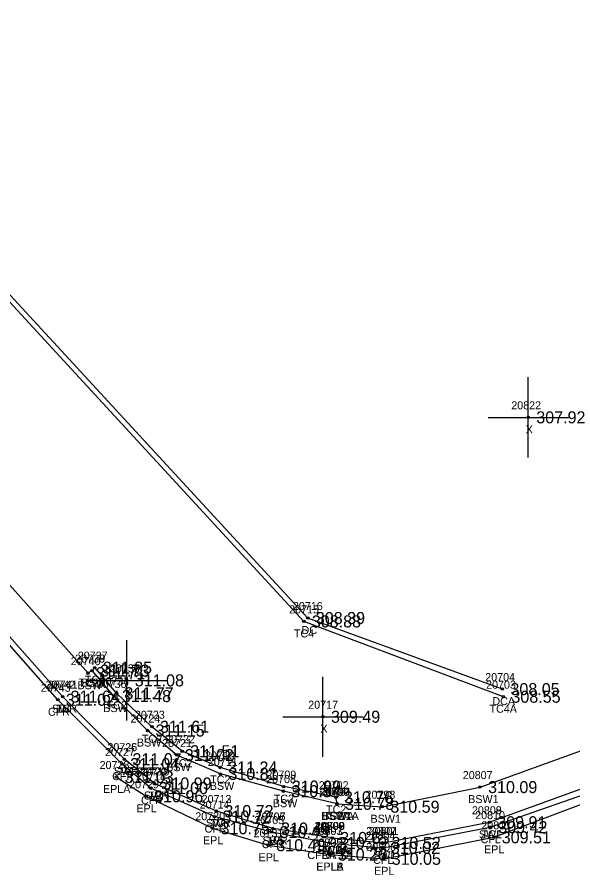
# Model space of a CAD drawing. Extents: x 1970242 to 1971082, y 803104 to 803947.
# Drawn here: x 1970579.6 to 1970648.9, y 803614.4 to 803721.5 of the extents above; entities that cross this region are included whole.
import ezdxf

# ---------------------------------------------------------------- set-up
doc = ezdxf.new("R2010")
doc.units = 0
for name, color, linetype in [('RD_DTM_BkLn2', 7, 'Continuous'), ('RD_EX_Conc', 7, 'Continuous'), ('RD_EX_Conc_txCode', 7, 'Continuous'), ('RD_EX_Misc', 7, 'Continuous'), ('RD_EX_Misc_txCode', 7, 'Continuous'), ('RD_EX_Road', 7, 'Continuous'), ('RD_EX_Road_txCode', 7, 'Continuous'), ('RD_EX_TX_Conc_ELEV', 7, 'Continuous'), ('RD_EX_TX_Misc_ELEV', 7, 'Continuous'), ('RD_EX_TX_Road_ELEV', 7, 'Continuous'), ('RD_SMD_Locator', 7, 'Continuous')]:
    doc.layers.add(name, color=color, linetype=linetype)

msp = doc.modelspace()

# ---------------------------------------------------------------- linework, layer by layer
at = {"layer": 'RD_DTM_BkLn2'}
for points in [[(1970640.22, 803636.65), (1970615.32, 803646.05), (1970567.96, 803697.44), (1970561.94, 803699.47), (1970557.33, 803698.89), (1970545.39, 803690.43), (1970544.29, 803690.54)], [(1970618.86, 803619.02), (1970611.49, 803620.2), (1970604.41, 803622.38), (1970596.68, 803625.82), (1970592.94, 803628.85), (1970585.22, 803636.66), (1970542.35, 803685.17), (1970541.56, 803686.12)], [(1970618.86, 803619.02), (1970625.27, 803618.4), (1970638.45, 803620.98), (1970653.93, 803626.63), (1970665.79, 803631.9), (1970699.28, 803647.11), (1970716.76, 803654.07), (1970733.36, 803660.46), (1970737.6, 803661.87)], [(1970619.46, 803623.28), (1970619.33, 803624.1), (1970612.82, 803625.43), (1970604.88, 803627.82), (1970600.14, 803629.85), (1970596.37, 803632.9), (1970591.95, 803637.08), (1970589.24, 803640.28), (1970588.91, 803639.91)]]:
    msp.add_lwpolyline(points, dxfattribs=at)
at = {"layer": 'RD_EX_Conc'}
for points in [[(1970640.1, 803637.6), (1970615.82, 803646.47), (1970568.4, 803697.87), (1970561.49, 803700.09), (1970556.78, 803699.45), (1970544.29, 803690.54)], [(1970619.46, 803623.28), (1970612.77, 803624.86), (1970604.91, 803627.02), (1970599.47, 803629.36), (1970595.82, 803632.43), (1970591.62, 803636.73), (1970588.91, 803639.91), (1970588.4, 803639.59), (1970556.38, 803675.53), (1970556.93, 803675.97), (1970554.39, 803679.06), (1970544.29, 803690.54)], [(1970618.57, 803618.39), (1970611.3, 803619.75), (1970604.17, 803621.69), (1970596.23, 803625.24), (1970592.64, 803628.24), (1970584.63, 803636.27), (1970541.45, 803685.26)], [(1970618.86, 803619.02), (1970611.49, 803620.2), (1970604.41, 803622.38), (1970596.68, 803625.82), (1970592.94, 803628.85), (1970585.22, 803636.66), (1970542.35, 803685.17), (1970541.56, 803686.12)], [(1970619.46, 803623.28), (1970625.12, 803622.92), (1970637.31, 803625.37), (1970651.91, 803630.64), (1970663.49, 803635.69), (1970697.74, 803651.1), (1970715.31, 803658.28), (1970731.61, 803664.68), (1970736.58, 803666.33)], [(1970618.86, 803619.02), (1970625.27, 803618.4), (1970638.45, 803620.98), (1970653.93, 803626.63), (1970665.79, 803631.9), (1970699.28, 803647.11), (1970716.76, 803654.07), (1970733.36, 803660.46), (1970737.6, 803661.87)], [(1970618.57, 803618.39), (1970625.17, 803617.79), (1970638.58, 803620.37), (1970654.08, 803625.78), (1970666.26, 803631.23), (1970699.41, 803646.5), (1970717.02, 803653.29), (1970733.54, 803659.83), (1970737.45, 803661.48)]]:
    msp.add_lwpolyline(points, dxfattribs=at)
at = {"layer": 'RD_EX_Misc'}
for p, q in [((1970643.32, 803666.52), (1970643.32, 803676.52)), ((1970638.32, 803671.52), (1970648.32, 803671.52)), ((1970593.23, 803633.69), (1970593.23, 803643.69)), ((1970617.71, 803629.15), (1970617.71, 803639.15)), ((1970588.23, 803638.69), (1970598.23, 803638.69)), ((1970612.71, 803634.15), (1970622.71, 803634.15))]:
    msp.add_line(p, q, dxfattribs=at)
at = {"layer": 'RD_EX_Road'}
msp.add_lwpolyline([(1970591.95, 803626.63), (1970595.64, 803624.22), (1970603.94, 803620.23), (1970610.89, 803618.12), (1970618.56, 803616.95), (1970618.56, 803616.95), (1970625.29, 803616.42), (1970639.01, 803619.1), (1970654.35, 803624.92), (1970666.82, 803630.04), (1970700.04, 803645.21), (1970717.46, 803652.2), (1970737.46, 803660.02), (1970785.58, 803677.59), (1970806.16, 803685.61), (1970810.51, 803687.07), (1970832.41, 803695.41), (1970845.91, 803700.39), (1970902.88, 803721.47)], dxfattribs=at)
at = {"layer": 'RD_SMD_Locator'}
for centre in [(1970643.32, 803671.52), (1970615.82, 803646.47), (1970615.32, 803646.05), (1970589.24, 803640.28), (1970588.4, 803639.59), (1970588.91, 803639.91), (1970588.91, 803639.91), (1970593.23, 803638.69), (1970591.95, 803637.08), (1970640.1, 803637.6), (1970584.63, 803636.27), (1970585.22, 803636.66), (1970585.22, 803636.66), (1970591.62, 803636.73), (1970640.22, 803636.65), (1970617.71, 803634.15), (1970596.37, 803632.9), (1970595.82, 803632.43), (1970599.47, 803629.36), (1970600.14, 803629.85), (1970592.94, 803628.85), (1970592.94, 803628.85), (1970592.64, 803628.24), (1970604.88, 803627.82), (1970591.95, 803626.63), (1970604.91, 803627.02), (1970596.23, 803625.24), (1970596.68, 803625.82), (1970596.68, 803625.82), (1970612.82, 803625.43), (1970637.31, 803625.37), (1970595.64, 803624.22), (1970612.77, 803624.86), (1970619.33, 803624.1), (1970619.46, 803623.28), (1970619.46, 803623.28), (1970619.46, 803623.28), (1970625.12, 803622.92), (1970604.41, 803622.38), (1970604.41, 803622.38), (1970604.17, 803621.69), (1970638.45, 803620.98), (1970638.45, 803620.98), (1970603.94, 803620.23), (1970611.3, 803619.75), (1970611.49, 803620.2), (1970611.49, 803620.2), (1970638.58, 803620.37), (1970618.86, 803619.02), (1970618.86, 803619.02), (1970618.86, 803619.02), (1970618.86, 803619.02), (1970639.01, 803619.1), (1970610.89, 803618.12), (1970618.57, 803618.39), (1970618.57, 803618.39), (1970625.17, 803617.79), (1970625.27, 803618.4), (1970625.27, 803618.4), (1970618.56, 803616.95), (1970618.56, 803616.95), (1970625.29, 803616.42)]:
    msp.add_circle(centre, 0.15, dxfattribs=at)

# ---------------------------------------------------------------- texts
at = {"layer": 'RD_EX_Conc_txCode'}
for s, p in [('20715', (1970613.49, 803647.05)), ('20716', (1970613.96, 803647.47)), ('TC4', (1970614.08, 803644.05)), ('DC', (1970615.04, 803644.47)), ('20740', (1970586.24, 803640.59)), ('20738', (1970586.79, 803640.91)), ('20739', (1970586.79, 803640.91)), ('20737', (1970587.12, 803641.28)), ('TC2', (1970588, 803638.28)), ('20704', (1970637.95, 803638.6)), ('20743', (1970582.51, 803637.27)), ('20742', (1970583.1, 803637.66)), ('20741', (1970583.38, 803637.66)), ('BSW', (1970587.08, 803637.59)), ('TC2B', (1970587.19, 803637.91)), ('BSW', (1970587.59, 803637.91)), ('20736', (1970589.48, 803637.73)), ('20734', (1970589.83, 803638.08)), ('20703', (1970638.06, 803637.65)), ('TC2', (1970590.71, 803635.08)), ('DCA', (1970638.84, 803635.6)), ('CFR', (1970583.4, 803634.27)), ('SWR', (1970583.9, 803634.66)), ('TC', (1970584.42, 803634.66)), ('BSW', (1970590.3, 803634.73)), ('20723', (1970594.25, 803633.9)), ('TC4A', (1970638.49, 803634.65)), ('20724', (1970593.7, 803633.43)), ('TC2', (1970595.12, 803630.9)), ('20722', (1970598.02, 803630.85)), ('20726', (1970590.8, 803629.85)), ('20725', (1970590.82, 803629.85)), ('BSW', (1970594.5, 803630.43)), ('20721', (1970597.64, 803630.36)), ('20727', (1970590.52, 803629.24)), ('20710', (1970603, 803628.82)), ('TC2', (1970598.9, 803627.85)), ('20711', (1970603.35, 803628.02)), ('SWR', (1970591.62, 803626.85)), ('TC', (1970592.14, 803626.85)), ('20720', (1970594.53, 803626.82)), ('20719', (1970594.85, 803626.82)), ('BSW', (1970598.16, 803627.36)), ('20709', (1970610.66, 803626.43)), ('20807', (1970635.15, 803626.37)), ('CFR', (1970591.41, 803626.24)), ('20718', (1970594.4, 803626.24)), ('TC2', (1970603.63, 803625.82)), ('20708', (1970610.62, 803625.86)), ('BSW', (1970603.59, 803625.02)), ('20702', (1970617.18, 803625.1)), ('20700', (1970617.26, 803624.28)), ('20797', (1970617.34, 803624.28)), ('20701', (1970617.58, 803624.28)), ('CFR', (1970595, 803623.24)), ('SWR', (1970595.37, 803623.82)), ('TC', (1970595.89, 803623.82)), ('20712', (1970602.57, 803623.38)), ('20713', (1970602.57, 803623.38)), ('TC2', (1970611.57, 803623.43)), ('20798', (1970623.01, 803623.92)), ('BSW1', (1970635.82, 803623.37)), ('20714', (1970602.33, 803622.69)), ('BSW', (1970611.46, 803622.86)), ('TC2', (1970618.09, 803622.1)), ('20706', (1970609.31, 803621.2)), ('20707', (1970609.33, 803621.2)), ('BSW1A', (1970617.49, 803621.28)), ('BSWA', (1970617.65, 803621.28)), ('TC2A', (1970617.73, 803621.28)), ('20808', (1970636.29, 803621.98)), ('20809', (1970636.29, 803621.98)), ('20810', (1970636.7, 803621.37)), ('SWR', (1970603.09, 803620.38)), ('TC', (1970603.61, 803620.38)), ('20705', (1970609.15, 803620.75)), ('20800', (1970616.66, 803620.02)), ('20698', (1970616.71, 803620.02)), ('20699', (1970616.71, 803620.02)), ('20799', (1970616.74, 803620.02)), ('BSW1', (1970623.64, 803620.92)), ('CFR', (1970602.94, 803619.69)), ('20803', (1970616.41, 803619.39)), ('20697', (1970616.43, 803619.39)), ('20802', (1970623.11, 803619.4)), ('20801', (1970623.4, 803619.4)), ('SWL', (1970637.16, 803618.98)), ('TC1', (1970637.49, 803618.98)), ('CFR', (1970610.07, 803617.75)), ('SWR', (1970610.17, 803618.2)), ('TC', (1970610.69, 803618.2)), ('20804', (1970623.01, 803618.79)), ('CFL', (1970637.37, 803618.37)), ('SWRA', (1970617.05, 803617.02)), ('SWLA', (1970617.08, 803617.02)), ('TC1A', (1970617.41, 803617.02)), ('TCA', (1970617.57, 803617.02)), ('CFRA 12', (1970615.75, 803616.39)), ('CFLA 12', (1970615.77, 803616.39)), ('CFL', (1970623.96, 803615.79)), ('SWL', (1970623.98, 803616.4)), ('TC1', (1970624.31, 803616.4))]:
    msp.add_text(s, height=1, dxfattribs=at).set_placement(p)
at = {"layer": 'RD_EX_Misc_txCode'}
for s, p in [('20822', (1970641.2, 803672.52)), ('X', (1970643, 803669.52)), ('20735', (1970591.12, 803639.69)), ('X', (1970592.92, 803636.69)), ('20717', (1970615.87, 803635.15)), ('X', (1970617.39, 803632.15))]:
    msp.add_text(s, height=1, dxfattribs=at).set_placement(p)
at = {"layer": 'RD_EX_Road_txCode'}
for s, p in [('20728', (1970589.84, 803627.63)), ('EPLA', (1970590.26, 803624.63)), ('20729', (1970593.52, 803625.22)), ('EPL', (1970594.43, 803622.22)), ('20730', (1970601.78, 803621.23)), ('20811', (1970637.46, 803620.1)), ('20731', (1970609.05, 803619.12)), ('EPL', (1970602.74, 803618.23)), ('20805', (1970616.4, 803617.95)), ('20732', (1970616.44, 803617.95)), ('20806', (1970623.11, 803617.42)), ('EPL', (1970637.8, 803617.1)), ('EPL', (1970609.68, 803616.12)), ('EPLA', (1970616.86, 803614.95)), ('EPLB', (1970616.88, 803614.95)), ('EPL', (1970624.08, 803614.42))]:
    msp.add_text(s, height=1, dxfattribs=at).set_placement(p)
at = {"layer": 'RD_EX_TX_Conc_ELEV'}
for s, p in [('308.88', (1970616.32, 803645.3)), ('308.39', (1970616.82, 803645.72)), ('311.71', (1970589.4, 803638.84)), ('311.73', (1970589.91, 803639.16)), ('311.73', (1970589.91, 803639.16)), ('311.85', (1970590.24, 803639.53)), ('308.05', (1970641.1, 803636.85)), ('311.02', (1970585.63, 803635.52)), ('311.64', (1970586.22, 803635.91)), ('311.64', (1970586.22, 803635.91)), ('311.48', (1970592.62, 803635.98)), ('311.77', (1970592.95, 803636.33)), ('308.55', (1970641.22, 803635.9)), ('311.15', (1970596.82, 803631.68)), ('311.61', (1970597.37, 803632.15)), ('311.51', (1970601.14, 803629.1)), ('311.07', (1970593.94, 803628.1)), ('311.07', (1970593.94, 803628.1)), ('311.02', (1970600.47, 803628.61)), ('311.04', (1970593.64, 803627.49)), ('311.24', (1970605.88, 803627.07)), ('310.81', (1970605.91, 803626.27)), ('310.99', (1970597.68, 803625.07)), ('310.99', (1970597.68, 803625.07)), ('311.00', (1970597.23, 803624.49)), ('310.54', (1970613.77, 803624.11)), ('310.99', (1970613.82, 803624.68)), ('310.09', (1970638.31, 803624.62)), ('310.76', (1970620.33, 803623.35)), ('310.72', (1970605.41, 803621.63)), ('310.72', (1970605.41, 803621.63)), ('310.78', (1970620.46, 803622.53)), ('310.78', (1970620.46, 803622.53)), ('310.78', (1970620.46, 803622.53)), ('310.59', (1970626.12, 803622.17)), ('310.72', (1970605.17, 803620.94)), ('310.49', (1970612.49, 803619.45)), ('310.49', (1970612.49, 803619.45)), ('309.91', (1970639.45, 803620.23)), ('309.91', (1970639.45, 803620.23)), ('309.42', (1970639.58, 803619.62)), ('310.45', (1970612.3, 803619)), ('310.19', (1970619.57, 803617.64)), ('310.19', (1970619.57, 803617.64)), ('310.65', (1970619.86, 803618.27)), ('310.65', (1970619.86, 803618.27)), ('310.65', (1970619.86, 803618.27)), ('310.65', (1970619.86, 803618.27)), ('310.52', (1970626.27, 803617.65)), ('310.52', (1970626.27, 803617.65)), ('310.02', (1970626.17, 803617.04))]:
    msp.add_text(s, height=1.5, dxfattribs=at).set_placement(p)
at = {"layer": 'RD_EX_TX_Misc_ELEV'}
for s, p in [('307.92', (1970644.32, 803670.77)), ('311.08', (1970594.23, 803637.94)), ('309.49', (1970618.71, 803633.4))]:
    msp.add_text(s, height=1.5, dxfattribs=at).set_placement(p)
at = {"layer": 'RD_EX_TX_Road_ELEV'}
for s, p in [('311.03', (1970592.95, 803625.88)), ('310.96', (1970596.64, 803623.47)), ('310.75', (1970604.94, 803619.48)), ('309.51', (1970640.01, 803618.35)), ('310.49', (1970611.89, 803617.37)), ('310.26', (1970619.56, 803616.2)), ('310.26', (1970619.56, 803616.2)), ('310.05', (1970626.29, 803615.67))]:
    msp.add_text(s, height=1.5, dxfattribs=at).set_placement(p)

doc.saveas('drawing.dxf')
